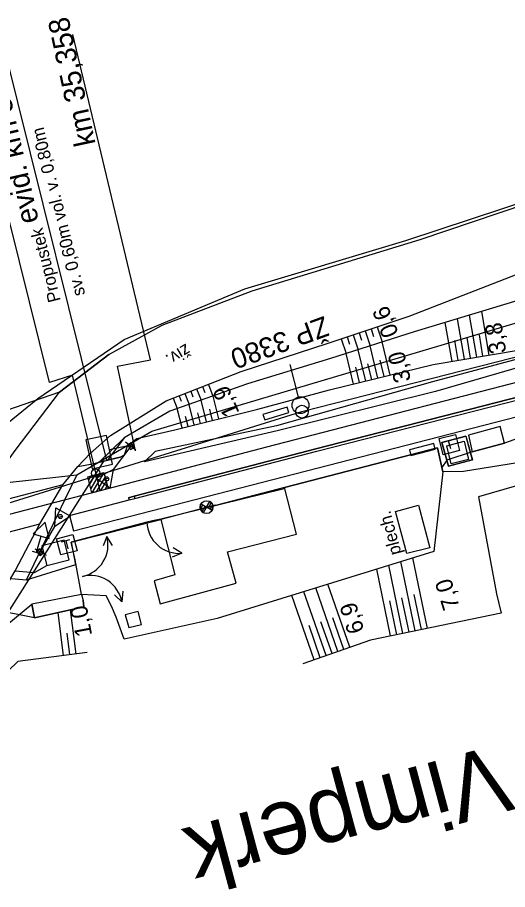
# Model space of a CAD drawing. Extents: x -806456 to -805395, y -1150847 to -1150506.
# Drawn here: x -806168.1 to -806109.7, y -1150752.4 to -1150648.6 of the extents above; entities that cross this region are included whole.
import ezdxf

# ---------------------------------------------------------------- set-up
doc = ezdxf.new("R2010")
doc.units = 0
for name, color, linetype in [('0381KM032-037P - Vrstva 1', 7, 'Continuous'), ('0381KM032-037P - Vrstva 12', 7, 'Continuous'), ('0381KM032-037P - Vrstva 14', 7, 'Continuous'), ('0381KM032-037P - Vrstva 16', 7, 'Continuous'), ('0381KM032-037P - Vrstva 17', 7, 'Continuous'), ('0381KM032-037P - Vrstva 19', 7, 'Continuous'), ('0381KM032-037P - Vrstva 23', 7, 'Continuous'), ('0381KM032-037P - Vrstva 27', 7, 'Continuous'), ('0381KM032-037P - Vrstva 3', 7, 'Continuous'), ('0381KM032-037P - Vrstva 33', 7, 'Continuous'), ('0381KM032-037P - Vrstva 36', 7, 'Continuous'), ('0381KM032-037P - Vrstva 4', 7, 'Continuous'), ('0381KM032-037P - Vrstva 48', 7, 'Continuous'), ('0381KM032-037P - Vrstva 49', 7, 'Continuous'), ('0381KM032-037P - Vrstva 51', 7, 'Continuous'), ('0381KM032-037P - Vrstva 55', 7, 'Continuous'), ('0381KM032-037P - Vrstva 7', 7, 'Continuous'), ('hran DP - hran DP', 7, 'Continuous'), ('vyt_sit - polygon', 7, 'Continuous'), ('vyt_sit - stávající', 7, 'Continuous')]:
    doc.layers.add(name, color=color, linetype=linetype)

msp = doc.modelspace()

# ---------------------------------------------------------------- linework, layer by layer
at = {"layer": '0381KM032-037P - Vrstva 1'}
msp.add_lwpolyline([(-805989.76, -1150661.17), (-806027.03, -1150670.9), (-806064.32, -1150680.56), (-806101.67, -1150690.24), (-806138.44, -1150699.75), (-806158.28, -1150704.94), (-806163.64, -1150706.34), (-806175.38, -1150709.4), (-806186.46, -1150712.29), (-806205.2, -1150717.19), (-806213.26, -1150719.29)], dxfattribs=at)
at = {"layer": '0381KM032-037P - Vrstva 12'}
for p, q in [((-806154.58, -1150699.23), (-806154.58, -1150699.23)), ((-806154.66, -1150700.03), (-806154.65, -1150700.03)), ((-806165.43, -1150711.84), (-806165.8, -1150712.11)), ((-806165.43, -1150711.84), (-806165.45, -1150711.85)), ((-806165.43, -1150711.84), (-806165.05, -1150712.37)), ((-806165.41, -1150712.64), (-806165.41, -1150712.64))]:
    msp.add_line(p, q, dxfattribs=at)
for points in [[(-806154.96, -1150699.45), (-806154.58, -1150699.23), (-806154.27, -1150699.81), (-806154.65, -1150700.03), (-806154.96, -1150699.45), (-806154.96, -1150699.45), (-806154.66, -1150700.03), (-806154.27, -1150699.81), (-806154.27, -1150699.81)], [(-806154.27, -1150699.81), (-806154.58, -1150699.23), (-806154.96, -1150699.45)], [(-806165.8, -1150712.11), (-806165.45, -1150711.85), (-806165.06, -1150712.37), (-806165.41, -1150712.64), (-806165.8, -1150712.11), (-806165.8, -1150712.11), (-806165.41, -1150712.64), (-806165.05, -1150712.37), (-806165.06, -1150712.37)]]:
    msp.add_lwpolyline(points, dxfattribs=at)
at = {"layer": '0381KM032-037P - Vrstva 14'}
for p, q in [((-806161.45, -1150709.69), (-806093.88, -1150692.3)), ((-806154.2, -1150705.57), (-806154.13, -1150705.84)), ((-806161.92, -1150707.86), (-806154.82, -1150706.03)), ((-806161.92, -1150707.86), (-806161.45, -1150709.69))]:
    msp.add_line(p, q, dxfattribs=at)
for points in [[(-806154.89, -1150705.76), (-806154.2, -1150705.57), (-806132.57, -1150699.95), (-806108.13, -1150693.69), (-806094.43, -1150690.13), (-806092.84, -1150689.77), (-806094.43, -1150690.13), (-806108.12, -1150693.69), (-806132.57, -1150699.95), (-806154.2, -1150705.57), (-806154.88, -1150705.76)], [(-806154.82, -1150706.03), (-806154.13, -1150705.84), (-806132.47, -1150700.24), (-806108.06, -1150693.98), (-806094.31, -1150690.42), (-806092.67, -1150690)], [(-806154.82, -1150706.03), (-806154.14, -1150705.84), (-806132.47, -1150700.24)], [(-806154.89, -1150705.76), (-806154.88, -1150705.76), (-806154.82, -1150706.03)]]:
    msp.add_lwpolyline(points, dxfattribs=at)
at = {"layer": '0381KM032-037P - Vrstva 16'}
for p, q in [((-806114.72, -1150698.42), (-806113.93, -1150701.24)), ((-806114.72, -1150698.42), (-806113.94, -1150701.24)), ((-806160.48, -1150717.28), (-806166.41, -1150718.42)), ((-806160.2, -1150718.76), (-806160.29, -1150717.98)), ((-806166.41, -1150718.42), (-806166.07, -1150720.05)), ((-806166.07, -1150720.05), (-806160.2, -1150718.76))]:
    msp.add_line(p, q, dxfattribs=at)
for points in [[(-806114.72, -1150698.42), (-806114.72, -1150698.42), (-806117.58, -1150699.2), (-806117.58, -1150699.2), (-806114.72, -1150698.42)], [(-806117.58, -1150699.2), (-806116.77, -1150702.02), (-806116.77, -1150702.02), (-806117.58, -1150699.2)], [(-806116.77, -1150702.02), (-806113.94, -1150701.24), (-806113.93, -1150701.24), (-806116.77, -1150702.02)], [(-806166.07, -1150720.05), (-806171.13, -1150719.06), (-806168.37, -1150714.46), (-806166.08, -1150714.66), (-806164.6, -1150713.82)]]:
    msp.add_lwpolyline(points, dxfattribs=at)
msp.add_lwpolyline([(-806153.75, -1150719.31), (-806155.27, -1150719.69), (-806154.84, -1150721.22), (-806153.33, -1150720.86)], close=True, dxfattribs=at)
at = {"layer": '0381KM032-037P - Vrstva 17'}
for q in [(-806149.55, -1150711.72), (-806149.7, -1150712.83)]:
    msp.add_line((-806148.52, -1150712.37), q, dxfattribs=at)
for points in [[(-806169.28, -1150696.91), (-806165.68, -1150693.97), (-806155.41, -1150686.94), (-806141.03, -1150680.9), (-806121.85, -1150675.14), (-806106.33, -1150670.05), (-806095.39, -1150665.45)], [(-806136.29, -1150704.55), (-806118.08, -1150699.83), (-806117.57, -1150702.15), (-806117.47, -1150702.7)], [(-806160.48, -1150717.28), (-806161.23, -1150713.17), (-806161.72, -1150711.06), (-806151.04, -1150708.34)], [(-806156.8, -1150711.44), (-806157.46, -1150710.36), (-806157.92, -1150711.49)], [(-806155.55, -1150716.9), (-806155.67, -1150718.15), (-806156.57, -1150717.34)]]:
    msp.add_lwpolyline(points, dxfattribs=at)
for centre, start, end in [((-806148.87, -1150708.56), 181.714, 275.2338), ((-806161.16, -1150711.38), 281.9322, 15.4521), ((-806159.44, -1150718.85), 10.4818, 104.0016)]:
    msp.add_arc(centre, 3.83, start, end, dxfattribs=at)
at = {"layer": '0381KM032-037P - Vrstva 19'}
for p, q in [((-806157.45, -1150701.33), (-806169.59, -1150652.63)), ((-806169.99, -1150720.61), (-806157.73, -1150701.3)), ((-806158.4, -1150701.54), (-806157.37, -1150701.28)), ((-806158.4, -1150701.55), (-806158.4, -1150701.54)), ((-806157.37, -1150701.28), (-806157.37, -1150701.28))]:
    msp.add_line(p, q, dxfattribs=at)
for points in [[(-806158.98, -1150701.71), (-806155.86, -1150700.93), (-806157.37, -1150701.28)], [(-806158.98, -1150701.71), (-806158.4, -1150701.55)]]:
    msp.add_lwpolyline(points, dxfattribs=at)
at = {"layer": '0381KM032-037P - Vrstva 23'}
for p, q in [((-806110.63, -1150697.29), (-806114.4, -1150698.3)), ((-806110.1, -1150699.27), (-806110.63, -1150697.29)), ((-806114.4, -1150698.3), (-806113.94, -1150700.3)), ((-806116.98, -1150699.59), (-806114.92, -1150699.04)), ((-806116.46, -1150701.73), (-806116.98, -1150699.59)), ((-806113.94, -1150700.3), (-806110.1, -1150699.27))]:
    msp.add_line(p, q, dxfattribs=at)
for points in [[(-806138.87, -1150695.85), (-806138.67, -1150696.5), (-806135.81, -1150695.62), (-806136.01, -1150694.97)], [(-806121.43, -1150700.07), (-806121.26, -1150700.73), (-806118.36, -1150699.98), (-806118.53, -1150699.32)], [(-806142.07, -1150715.95), (-806143.1, -1150712.22), (-806134.89, -1150710.09), (-806136.29, -1150704.55), (-806144.53, -1150706.67), (-806144.58, -1150706.64), (-806151.04, -1150708.34), (-806149.37, -1150714.94), (-806151.84, -1150715.67), (-806151.1, -1150718.4)], [(-806119.02, -1150711.72), (-806121.75, -1150712.41), (-806123.08, -1150707.39), (-806120.35, -1150706.66)], [(-806162.56, -1150710.82), (-806165.2, -1150711.49), (-806164.6, -1150713.82), (-806161.96, -1150713.14)]]:
    msp.add_lwpolyline(points, close=True, dxfattribs=at)
msp.add_lwpolyline([(-806114.92, -1150699.04), (-806114.39, -1150701.22), (-806116.46, -1150701.73)], dxfattribs=at)
at = {"layer": '0381KM032-037P - Vrstva 27'}
msp.add_line((-806158.85, -1150702.83), (-806158.75, -1150702.83), dxfattribs=at)
msp.add_circle((-806158.8, -1150702.83), 0.5, dxfattribs=at)
at = {"layer": '0381KM032-037P - Vrstva 3'}
for p, q in [((-806157.82, -1150702.75), (-806159.25, -1150705.19)), ((-806159.36, -1150703.15), (-806159.65, -1150703.65)), ((-806158.84, -1150703.02), (-806159.52, -1150704.17)), ((-806158.33, -1150702.89), (-806159.38, -1150704.68)), ((-806157.68, -1150703.26), (-806158.73, -1150705.06)), ((-806157.55, -1150703.78), (-806158.22, -1150704.92)), ((-806157.42, -1150704.29), (-806157.71, -1150704.79))]:
    msp.add_line(p, q, dxfattribs=at)
msp.add_lwpolyline([(-806158.28, -1150704.94), (-806161.57, -1150691.16), (-806164.31, -1150692.07), (-806173.83, -1150653.81)], dxfattribs=at)
msp.add_lwpolyline([(-806157.31, -1150704.69), (-806159.25, -1150705.19), (-806159.75, -1150703.26), (-806157.82, -1150702.75)], close=True, dxfattribs=at)
at = {"layer": '0381KM032-037P - Vrstva 33'}
for p, q in [((-806117.29, -1150699.08), (-806116.32, -1150698.83)), ((-806116.8, -1150698.95), (-806116.55, -1150699.92)), ((-806162.85, -1150711), (-806161.88, -1150710.75)), ((-806162.37, -1150710.87), (-806162.11, -1150711.84))]:
    msp.add_line(p, q, dxfattribs=at)
for points in [[(-806117.9, -1150698.72), (-806115.96, -1150698.22), (-806115.46, -1150700.16), (-806117.4, -1150700.66), (-806117.9, -1150698.72)], [(-806163.46, -1150710.64), (-806161.52, -1150710.14), (-806161.02, -1150712.07), (-806162.96, -1150712.57), (-806163.46, -1150710.64)]]:
    msp.add_lwpolyline(points, dxfattribs=at)
at = {"layer": '0381KM032-037P - Vrstva 36'}
for p, q in [((-806134.65, -1150693.78), (-806135.65, -1150689.91)), ((-806134.4, -1150694.75), (-806134.4, -1150694.75))]:
    msp.add_line(p, q, dxfattribs=at)
msp.add_circle((-806134.4, -1150694.75), 1, dxfattribs=at)
at = {"layer": '0381KM032-037P - Vrstva 4'}
for p, q in [((-806154, -1150700.09), (-806155.24, -1150699.16)), ((-806157.25, -1150703.49), (-806157.74, -1150703.55)), ((-806163.25, -1150708.06), (-806162.78, -1150707.94)), ((-806166.06, -1150711.83), (-806164.71, -1150712.61))]:
    msp.add_line(p, q, dxfattribs=at)
for points in [[(-806107.83, -1150689.09), (-806118.69, -1150691.97), (-806137.28, -1150697.2), (-806151.73, -1150700.28), (-806152.97, -1150701.48)], [(-806107.78, -1150690.05), (-806118.34, -1150693.12), (-806137.19, -1150697.81), (-806152.97, -1150701.48)], [(-806154.62, -1150699.62), (-806156.7, -1150702.41), (-806157.11, -1150704.61), (-806158.72, -1150703.42), (-806156.7, -1150702.41)], [(-806165.39, -1150712.22), (-806163.66, -1150709.2), (-806163.53, -1150706.97), (-806161.79, -1150707.95), (-806163.66, -1150709.2)]]:
    msp.add_lwpolyline(points, dxfattribs=at)
msp.add_lwpolyline([(-806165.45, -1150708.87), (-806162.71, -1150704.24), (-806173.36, -1150707), (-806176.79, -1150711.84)], close=True, dxfattribs=at)
for centre in [(-806157.5, -1150703.52), (-806163.01, -1150708)]:
    msp.add_circle(centre, 0.248, dxfattribs=at)
at = {"layer": '0381KM032-037P - Vrstva 48'}
for p, q in [((-806113.41, -1150689.04), (-806114.26, -1150684.02)), ((-806111.93, -1150688.79), (-806112.81, -1150683.59)), ((-806116.36, -1150689.54), (-806117.16, -1150684.89)), ((-806114.89, -1150689.29), (-806115.71, -1150684.46)), ((-806127.43, -1150686.13), (-806127.13, -1150687.02)), ((-806126.71, -1150685.89), (-806126.12, -1150687.69)), ((-806126, -1150685.66), (-806125.7, -1150686.56)), ((-806125.29, -1150685.42), (-806124.69, -1150687.23)), ((-806129.56, -1150686.84), (-806128.97, -1150688.61)), ((-806128.85, -1150686.6), (-806128.55, -1150687.49)), ((-806128.14, -1150686.37), (-806127.55, -1150688.15)), ((-806115.63, -1150689.42), (-806116.03, -1150687.05)), ((-806114.15, -1150689.16), (-806114.57, -1150686.7)), ((-806112.67, -1150688.91), (-806113.1, -1150686.36)), ((-806126.64, -1150691.88), (-806127.54, -1150688.15)), ((-806125.18, -1150691.52), (-806126.11, -1150687.69)), ((-806123.72, -1150691.17), (-806124.68, -1150687.23)), ((-806128.09, -1150692.23), (-806128.97, -1150688.61)), ((-806127.36, -1150692.05), (-806127.81, -1150690.22)), ((-806125.91, -1150691.7), (-806126.37, -1150689.81)), ((-806124.45, -1150691.34), (-806124.92, -1150689.4)), ((-806145.37, -1150692.27), (-806144.83, -1150693.66)), ((-806148.17, -1150693.36), (-806147.66, -1150694.66)), ((-806147.47, -1150693.09), (-806147.21, -1150693.75)), ((-806146.77, -1150692.81), (-806146.24, -1150694.16)), ((-806146.07, -1150692.54), (-806145.8, -1150693.23)), ((-806149.56, -1150693.91), (-806149.08, -1150695.16)), ((-806148.86, -1150693.63), (-806148.62, -1150694.27)), ((-806145.6, -1150696.74), (-806146.24, -1150694.16)), ((-806144.14, -1150696.38), (-806144.82, -1150693.66)), ((-806148.51, -1150697.46), (-806149.08, -1150695.16)), ((-806147.05, -1150697.1), (-806147.66, -1150694.66)), ((-806144.87, -1150696.56), (-806145.2, -1150695.23)), ((-806147.78, -1150697.28), (-806148.08, -1150696.09)), ((-806146.33, -1150696.92), (-806146.64, -1150695.66)), ((-806119.26, -1150721.31), (-806121.01, -1150712.92)), ((-806122.2, -1150721.92), (-806123.88, -1150713.81)), ((-806120.73, -1150721.61), (-806122.45, -1150713.36)), ((-806123.67, -1150722.22), (-806125.32, -1150714.26)), ((-806128.52, -1150723.57), (-806131.14, -1150716.06)), ((-806131.36, -1150724.56), (-806134.01, -1150716.95)), ((-806129.94, -1150724.07), (-806132.57, -1150716.5)), ((-806120, -1150721.46), (-806120.86, -1150717.3)), ((-806132.77, -1150725.05), (-806135.44, -1150717.39)), ((-806122.93, -1150722.07), (-806123.77, -1150718.05)), ((-806121.46, -1150721.76), (-806122.32, -1150717.68)), ((-806161.12, -1150724.38), (-806161.8, -1150719.11)), ((-806162.61, -1150724.57), (-806163.27, -1150719.43)), ((-806129.23, -1150723.82), (-806130.54, -1150720.05)), ((-806132.07, -1150724.81), (-806133.39, -1150720.99)), ((-806130.65, -1150724.31), (-806131.97, -1150720.52)), ((-806161.86, -1150724.47), (-806162.2, -1150721.87))]:
    msp.add_line(p, q, dxfattribs=at)
at = {"layer": '0381KM032-037P - Vrstva 49'}
for q in [(-806158.4, -1150701.55), (-806157.37, -1150701.28)]:
    msp.add_line((-806155.41, -1150698.65), q, dxfattribs=at)
for points in [[(-806106.83, -1150681.79), (-806120.86, -1150686.01), (-806130.84, -1150689.2), (-806140.72, -1150692.22), (-806149.98, -1150695.47), (-806155.41, -1150698.65)], [(-806160.94, -1150702.04), (-806159.44, -1150700.5), (-806157.04, -1150698.34), (-806150.42, -1150694.24), (-806141.48, -1150690.75), (-806131.12, -1150687.36), (-806121.48, -1150684.16)], [(-806155.86, -1150700.93), (-806155.37, -1150700.64), (-806154.96, -1150699.45), (-806154.58, -1150699.23), (-806153.89, -1150698.71), (-806149.38, -1150697.67), (-806139.49, -1150695.22), (-806130.93, -1150692.92), (-806118.59, -1150689.92), (-806108.26, -1150688.17)], [(-806157.22, -1150688.72), (-806163.11, -1150693.21), (-806169.4, -1150695.38), (-806175.56, -1150698.03), (-806181.81, -1150705.21), (-806196.09, -1150709.85), (-806203.77, -1150712.23), (-806204.39, -1150713.54)], [(-806086.94, -1150691.89), (-806103.09, -1150696.78), (-806110.1, -1150699.27), (-806113.94, -1150700.3), (-806116.98, -1150701.29), (-806117.57, -1150702.15), (-806117.47, -1150702.7), (-806118.52, -1150712.15), (-806144.33, -1150720.15), (-806155.42, -1150722.6), (-806156.37, -1150719.96), (-806156.92, -1150718.66), (-806157.56, -1150717.45), (-806160.48, -1150717.28), (-806160.29, -1150717.98), (-806160.2, -1150718.76), (-806166.07, -1150720.05), (-806166.41, -1150718.42)], [(-806083.69, -1150697.11), (-806113.19, -1150705.65), (-806111.06, -1150717.22), (-806110.51, -1150719.49), (-806126.08, -1150722.72), (-806134.13, -1150725.52)], [(-806160.94, -1150702.04), (-806158.98, -1150701.71)], [(-806169.99, -1150720.61), (-806169.36, -1150720.88), (-806166.41, -1150718.42)], [(-806159.8, -1150724.2), (-806168.07, -1150725.27), (-806174.06, -1150731)]]:
    msp.add_lwpolyline(points, dxfattribs=at)
at = {"layer": '0381KM032-037P - Vrstva 51'}
msp.add_line((-806166.34, -1150712.11), (-806165.38, -1150712.39), dxfattribs=at)
for points in [[(-806140.16, -1150681.15), (-806120.15, -1150675.05), (-806107.44, -1150670.76), (-806090.7, -1150663.5), (-806064.75, -1150649.45)], [(-806121.48, -1150684.16), (-806105.03, -1150677.76), (-806088.01, -1150669.6), (-806061.17, -1150655.26)], [(-806195.22, -1150723.44), (-806183.65, -1150718.08), (-806179.48, -1150714.68), (-806176.79, -1150711.84), (-806173.36, -1150707), (-806168.38, -1150700.15), (-806163.11, -1150693.21), (-806157.22, -1150688.72), (-806150.87, -1150685.21), (-806140.16, -1150681.15)], [(-806194.18, -1150731.58), (-806186.23, -1150728.98), (-806178.59, -1150724.92), (-806174.21, -1150722.04), (-806171.13, -1150719.06), (-806168.37, -1150714.46), (-806165.45, -1150708.87), (-806162.71, -1150704.24), (-806160.94, -1150702.04), (-806159.44, -1150700.5), (-806157.04, -1150698.34), (-806150.42, -1150694.24), (-806141.48, -1150690.75), (-806131.12, -1150687.36), (-806121.48, -1150684.16)], [(-806165.86, -1150712.25), (-806165.3, -1150710.34), (-806164.34, -1150710.62), (-806164.8, -1150708.66), (-806166.26, -1150710.05), (-806165.3, -1150710.34)]]:
    msp.add_lwpolyline(points, dxfattribs=at)
at = {"layer": '0381KM032-037P - Vrstva 55'}
msp.add_lwpolyline([(-806161.05, -1150703.03), (-806162.49, -1150706.04), (-806167.06, -1150715.57)], dxfattribs=at)
at = {"layer": '0381KM032-037P - Vrstva 7'}
msp.add_line((-806154.06, -1150700.18), (-806154.37, -1150698.71), dxfattribs=at)
for points in [[(-806154.21, -1150699.44), (-806156.18, -1150690.11), (-806152.27, -1150689.34), (-806161.51, -1150650.62)], [(-806154.21, -1150699.44), (-806157.15, -1150700.08), (-806157.52, -1150698.37), (-806159.96, -1150698.89), (-806159.22, -1150702.31), (-806156.78, -1150701.79), (-806157.15, -1150700.08)]]:
    msp.add_lwpolyline(points, dxfattribs=at)
at = {"layer": 'hran DP - hran DP'}
for p, q in [((-806152.11, -1150697.83), (-806107.35, -1150684.54)), ((-806161.05, -1150703.03), (-806152.11, -1150697.83)), ((-806092.7, -1150699.08), (-806114.99, -1150702.66)), ((-806118.08, -1150699.83), (-806136.29, -1150704.55)), ((-806117.47, -1150702.7), (-806118.08, -1150699.83)), ((-806114.99, -1150702.66), (-806117.47, -1150702.7)), ((-806170.06, -1150704.04), (-806162.48, -1150703.19)), ((-806162.48, -1150703.19), (-806161.05, -1150703.03)), ((-806136.51, -1150704.75), (-806151.02, -1150708.33)), ((-806136.29, -1150704.55), (-806136.51, -1150704.75)), ((-806152.7, -1150708.67), (-806161.72, -1150711.06)), ((-806152.01, -1150708.53), (-806152.7, -1150708.67)), ((-806151.02, -1150708.33), (-806152.01, -1150708.53)), ((-806161.72, -1150711.06), (-806161.18, -1150713.76)), ((-806161.18, -1150713.76), (-806167.06, -1150715.57)), ((-806167.06, -1150715.57), (-806169.25, -1150715.39))]:
    msp.add_line(p, q, dxfattribs=at)
at = {"layer": 'vyt_sit - polygon'}
for p, q in [((-806134.24, -1150695.52), (-806002.92, -1150661.86)), ((-806238.54, -1150728.04), (-806134.24, -1150695.52))]:
    msp.add_line(p, q, dxfattribs=at)
at = {"layer": 'vyt_sit - stávající'}
for p, q in [((-806134.29, -1150695.52), (-806134.19, -1150695.52)), ((-806146.31, -1150707.13), (-806146.02, -1150706.63)), ((-806146.25, -1150706.5), (-806145.59, -1150706.88)), ((-806146.13, -1150707.42), (-806145.76, -1150706.78)), ((-806145.59, -1150706.88), (-806145.98, -1150707.54)), ((-806145.59, -1150706.88), (-806145.2, -1150706.22)), ((-806144.93, -1150707.27), (-806145.59, -1150706.88)), ((-806145.41, -1150706.99), (-806145.04, -1150706.36)), ((-806145.15, -1150707.14), (-806144.86, -1150706.65))]:
    msp.add_line(p, q, dxfattribs=at)
for centre, radius in [((-806134.24, -1150695.52), 0.756), ((-806145.59, -1150706.88), 0.764)]:
    msp.add_circle(centre, radius, dxfattribs=at)
for radius, start, end in [(0.764, 149.1827, 239.5007), (0.765, 329.8715, 59.765)]:
    msp.add_arc((-806145.59, -1150706.88), radius, start, end, dxfattribs=at)

# ---------------------------------------------------------------- texts
at = {"layer": '0381KM032-037P - Vrstva 19'}
for s, height, rotation, p in [('evid. km 35,365', 2.5, 102.9112, (-806165.54, -1150672.85)), ('sv. 0,60m vol. v. 0,80m', 1.5, 104.006, (-806160.03, -1150681.57)), ('Propustek', 1.5, 104.006, (-806162.95, -1150682.3))]:
    msp.add_text(s, height=height, rotation=rotation, dxfattribs=at).set_placement(p)
at = {"layer": '0381KM032-037P - Vrstva 23'}
for s, height, rotation, p in [('plech.', 1.5, 104.8456, (-806122.36, -1150712.38)), ('zast. Vimperk', 8, 195, (-806086.07, -1150728.44))]:
    msp.add_text(s, height=height, rotation=rotation, dxfattribs=at).set_placement(p)
at = {"layer": '0381KM032-037P - Vrstva 48'}
for s, rotation, p in [('0,6', 111.6516, (-806122.68, -1150686.22)), ('3,8', 99.6413, (-806109.88, -1150688.46)), ('3,0', 103.6676, (-806121.23, -1150691.81)), ('1,9', 113.3162, (-806141.64, -1150695.64)), ('7,0', 107.0974, (-806115.43, -1150718.78)), ('6,9', 106.8709, (-806126.79, -1150721.6)), ('1,0', 100.6308, (-806159.21, -1150722.11))]:
    msp.add_text(s, height=2, rotation=rotation, dxfattribs=at).set_placement(p)
at = {"layer": '0381KM032-037P - Vrstva 51'}
msp.add_text('živ.', height=1.5, rotation=210.724, dxfattribs=at).set_placement((-806148.04, -1150687.37))
at = {"layer": '0381KM032-037P - Vrstva 7'}
msp.add_text('km 35,358', height=2.5, rotation=102.1594, dxfattribs=at).set_placement((-806158.79, -1150663.65))
at = {"layer": 'vyt_sit - stávající'}
msp.add_text('ŽP 3380', height=2.4, rotation=200, dxfattribs=at).set_placement((-806131.56, -1150684.11))

doc.saveas('drawing.dxf')
